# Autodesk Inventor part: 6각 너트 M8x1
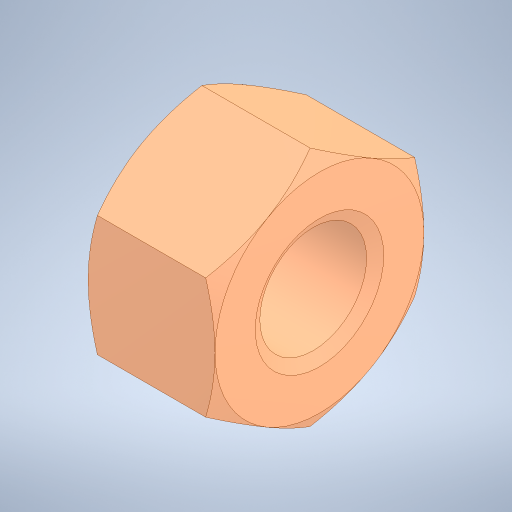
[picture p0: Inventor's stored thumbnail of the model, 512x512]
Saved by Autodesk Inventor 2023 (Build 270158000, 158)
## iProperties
Created: 2025-10
Part Number: 6각 너트 M8x1
Material: 강철, 연강
Description: 6각 너트 및 6각 가는 너트
Document SubType Name: Modeling
Designer: home
Density: 7.85 g/cm^3
Appearance: 기본값
Author: jhkim
Sending System: Autodesk Inventor 2026
Preprocessor: ST-DEVELOPER v20.1
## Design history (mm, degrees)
sketch "스케치1"
  geometry: 1 further point
  constraints: 1 other
feature "Solid1"
node "솔리드1"
